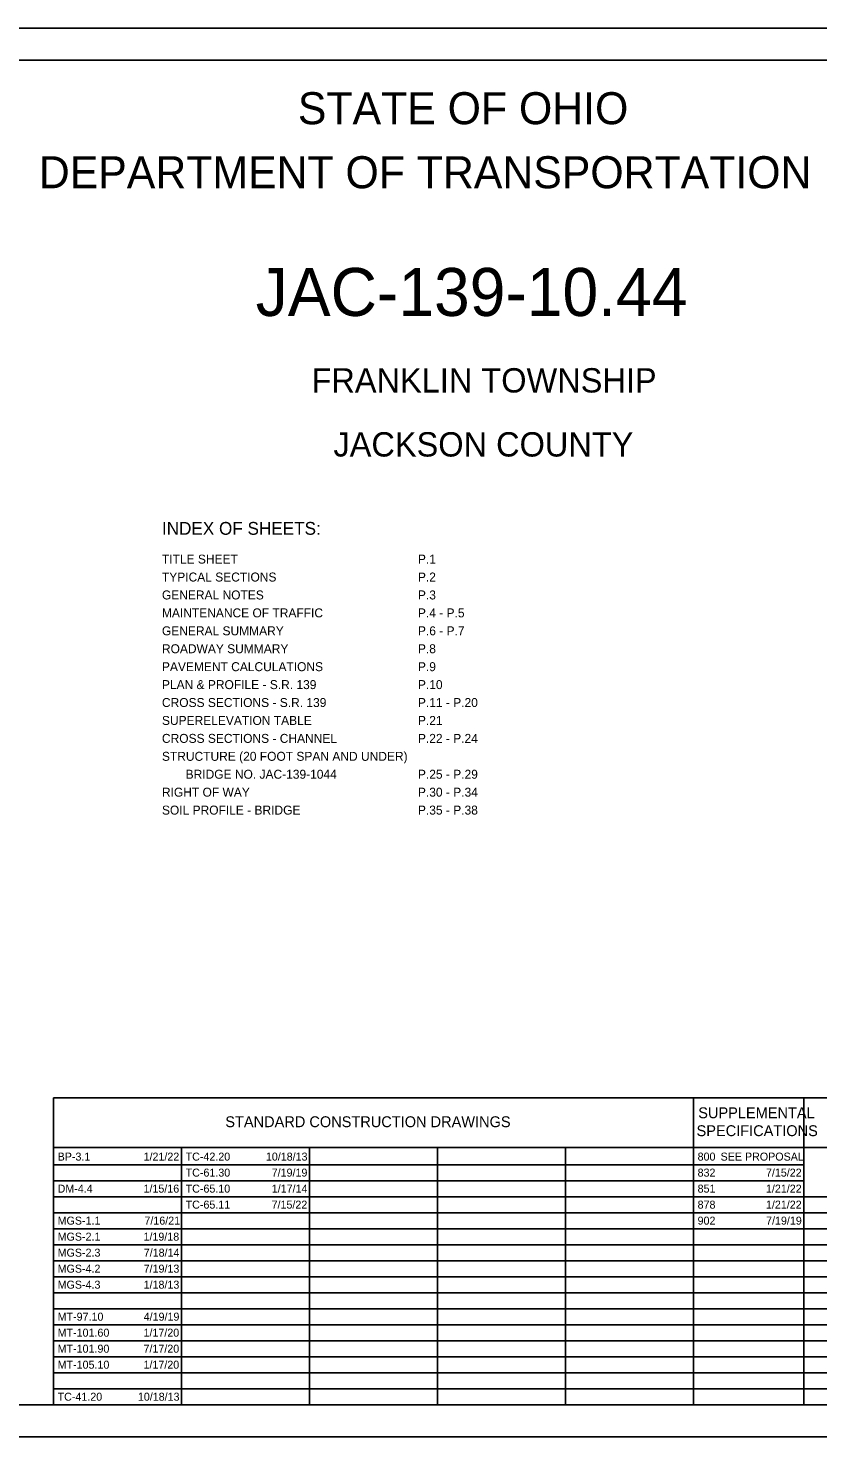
# Model space of a CAD drawing. Extents: x 0 to 34, y 0 to 22.
# Drawn here: x 9.75 to 22.09, y 0 to 22 of the extents above; entities that cross this region are included whole.
import ezdxf

# ---------------------------------------------------------------- set-up
doc = ezdxf.new("R2010")
doc.units = 0
for name, color, linetype in [('SH_Border', 7, 'Continuous'), ('SH_Cut_Line', 7, 'Continuous'), ('SH_Data', 7, 'Continuous'), ('SH_Text', 7, 'Continuous')]:
    doc.layers.add(name, color=color, linetype=linetype)

msp = doc.modelspace()

# ---------------------------------------------------------------- linework, layer by layer
at = {"layer": 'SH_Border'}
msp.add_lwpolyline([(1.5, 21.5), (33.5, 21.5), (33.5, 0.5), (1.5, 0.5)], close=True, dxfattribs=at)
at = {"layer": 'SH_Cut_Line'}
msp.add_lwpolyline([(0, 0), (34, 0), (34, 22), (0, 22)], close=True, dxfattribs=at)
at = {"layer": 'SH_Data'}
for p, q in [((10.15, 5.292), (23.6, 5.292)), ((10.15, 0.5), (10.15, 5.292)), ((20.15, 0.5), (20.15, 5.292)), ((21.875, 0.5), (21.875, 5.292)), ((10.15, 4.521), (23.6, 4.521)), ((12.15, 0.5), (12.15, 4.521)), ((14.15, 0.5), (14.15, 4.521)), ((16.15, 0.5), (16.15, 4.521)), ((18.15, 0.5), (18.15, 4.521)), ((10.15, 4.25), (21.875, 4.25)), ((10.15, 4), (21.875, 4)), ((10.15, 3.75), (23.6, 3.75)), ((10.15, 3.5), (23.6, 3.5)), ((10.15, 3.25), (23.6, 3.25)), ((10.15, 3), (23.6, 3)), ((10.15, 2.75), (23.6, 2.75)), ((10.15, 2.5), (23.6, 2.5)), ((10.15, 2.25), (23.6, 2.25)), ((10.15, 2), (23.6, 2)), ((10.15, 1.75), (23.6, 1.75)), ((10.15, 1.5), (23.6, 1.5)), ((10.15, 1.25), (23.6, 1.25)), ((10.15, 1), (23.6, 1)), ((10.15, 0.75), (23.6, 0.75))]:
    msp.add_line(p, q, dxfattribs=at)

# ---------------------------------------------------------------- texts
at = {"layer": 'SH_Text'}
for s, height, p in [('STATE OF OHIO', 0.5, (13.968, 20.5)), ('DEPARTMENT OF TRANSPORTATION', 0.5, (9.92, 19.5)), ('JAC-139-10.44', 0.75, (13.309, 17.505)), ('FRANKLIN TOWNSHIP', 0.38, (14.181, 16.31)), ('JACKSON COUNTY', 0.38, (14.524, 15.31)), ('INDEX OF SHEETS:', 0.2, (11.844, 14.088)), ('TITLE SHEET', 0.14, (11.844, 13.638)), ('P.1', 0.14, (15.844, 13.638)), ('TYPICAL SECTIONS', 0.14, (11.844, 13.358)), ('P.2', 0.14, (15.844, 13.358)), ('GENERAL NOTES', 0.14, (11.844, 13.078)), ('P.3', 0.14, (15.844, 13.078)), ('MAINTENANCE OF TRAFFIC', 0.14, (11.844, 12.798)), ('P.4 - P.5', 0.14, (15.844, 12.798)), ('GENERAL SUMMARY', 0.14, (11.844, 12.518)), ('P.6 - P.7', 0.14, (15.844, 12.518)), ('ROADWAY SUMMARY', 0.14, (11.844, 12.238)), ('P.8', 0.14, (15.844, 12.238)), ('PAVEMENT CALCULATIONS', 0.14, (11.844, 11.958)), ('P.9', 0.14, (15.844, 11.958)), ('PLAN & PROFILE - S.R. 139', 0.14, (11.844, 11.678)), ('P.10', 0.14, (15.844, 11.678)), ('CROSS SECTIONS - S.R. 139', 0.14, (11.844, 11.398)), ('P.11 - P.20', 0.14, (15.844, 11.398)), ('SUPERELEVATION TABLE', 0.14, (11.844, 11.118)), ('P.21', 0.14, (15.844, 11.118)), ('CROSS SECTIONS - CHANNEL', 0.14, (11.844, 10.838)), ('P.22 - P.24', 0.14, (15.844, 10.838)), ('STRUCTURE (20 FOOT SPAN AND UNDER)', 0.14, (11.844, 10.558)), ('BRIDGE NO. JAC-139-1044', 0.14, (12.214, 10.278)), ('P.25 - P.29', 0.14, (15.844, 10.278)), ('RIGHT OF WAY', 0.14, (11.844, 9.998)), ('P.30 - P.34', 0.14, (15.844, 9.998)), ('SOIL PROFILE - BRIDGE', 0.14, (11.844, 9.718)), ('P.35 - P.38', 0.14, (15.844, 9.718)), ('SUPPLEMENTAL', 0.17, (20.224, 4.976)), ('STANDARD CONSTRUCTION DRAWINGS', 0.17, (12.834, 4.836)), ('SPECIFICATIONS', 0.17, (20.198, 4.696)), ('BP-3.1', 0.125, (10.214, 4.314)), ('1/21/22', 0.125, (11.557, 4.314)), ('TC-42.20', 0.125, (12.214, 4.314)), ('10/18/13', 0.125, (13.468, 4.314)), ('800', 0.125, (20.214, 4.314)), ('SEE PROPOSAL', 0.125, (20.573, 4.314)), ('TC-61.30', 0.125, (12.214, 4.064)), ('7/19/19', 0.125, (13.559, 4.064)), ('832', 0.125, (20.214, 4.064)), ('7/15/22', 0.125, (21.282, 4.064)), ('DM-4.4', 0.125, (10.214, 3.814)), ('1/15/16', 0.125, (11.556, 3.814)), ('TC-65.10', 0.125, (12.214, 3.814)), ('1/17/14', 0.125, (13.56, 3.814)), ('851', 0.125, (20.214, 3.814)), ('1/21/22', 0.125, (21.282, 3.814)), ('TC-65.11', 0.125, (12.214, 3.564)), ('7/15/22', 0.125, (13.557, 3.564)), ('878', 0.125, (20.214, 3.564)), ('1/21/22', 0.125, (21.282, 3.564)), ('MGS-1.1', 0.125, (10.214, 3.314)), ('7/16/21', 0.125, (11.57, 3.314)), ('902', 0.125, (20.214, 3.314)), ('7/19/19', 0.125, (21.284, 3.314)), ('MGS-2.1', 0.125, (10.214, 3.064)), ('1/19/18', 0.125, (11.556, 3.064)), ('MGS-2.3', 0.125, (10.214, 2.814)), ('7/18/14', 0.125, (11.56, 2.814)), ('MGS-4.2', 0.125, (10.214, 2.564)), ('7/19/13', 0.125, (11.558, 2.564)), ('MGS-4.3', 0.125, (10.214, 2.314)), ('1/18/13', 0.125, (11.558, 2.314)), ('MT-97.10', 0.125, (10.214, 1.814)), ('4/19/19', 0.125, (11.559, 1.814)), ('MT-101.60', 0.125, (10.214, 1.564)), ('1/17/20', 0.125, (11.556, 1.564)), ('MT-101.90', 0.125, (10.214, 1.314)), ('7/17/20', 0.125, (11.556, 1.314)), ('MT-105.10', 0.125, (10.214, 1.064)), ('1/17/20', 0.125, (11.556, 1.064)), ('TC-41.20', 0.125, (10.214, 0.564)), ('10/18/13', 0.125, (11.468, 0.564))]:
    msp.add_text(s, height=height, dxfattribs=at).set_placement(p)

doc.saveas('drawing.dxf')
